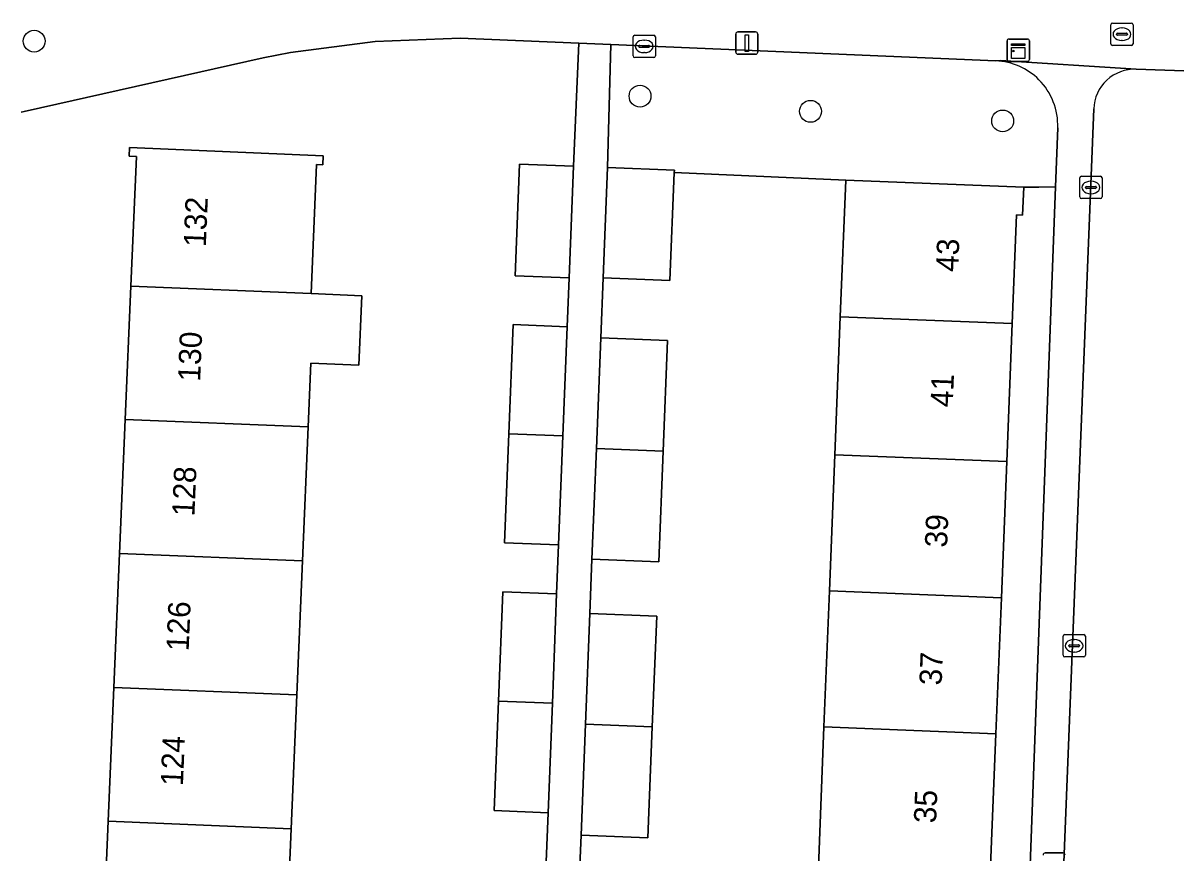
# Model space of a CAD drawing. Extents: x 161354 to 162026, y 386504 to 387460.
# Drawn here: x 161454.5 to 161506.1, y 387353.5 to 387390.7 of the extents above; entities that cross this region are included whole.
import ezdxf

# ---------------------------------------------------------------- set-up
doc = ezdxf.new("R2010")
doc.units = 0
for name, color, linetype in [('IMGEO_Boom', 7, 'Continuous'), ('IMGEO_Brandkraan', 7, 'Continuous'), ('IMGEO_Erf', 7, 'Continuous'), ('IMGEO_Groenvoorziening', 7, 'Continuous'), ('IMGEO_Kast', 7, 'Continuous'), ('IMGEO_Kolk', 7, 'Continuous'), ('IMGEO_Lichtmast', 7, 'Continuous'), ('IMGEO_Pand', 7, 'Continuous'), ('IMGEO_Pand_nummerreeks', 7, 'Continuous'), ('IMGEO_Rijbaan_lokaal_open', 7, 'Continuous'), ('IMGEO_Voetpad_open', 7, 'Continuous')]:
    doc.layers.add(name, color=color, linetype=linetype)

msp = doc.modelspace()

# ---------------------------------------------------------------- linework, layer by layer
at = {"layer": 'IMGEO_Boom'}
for centre in [(161454.969, 387389.906), (161482.122, 387387.443), (161489.765, 387386.761), (161498.375, 387386.331)]:
    msp.add_circle(centre, 0.489, dxfattribs=at)
at = {"layer": 'IMGEO_Brandkraan'}
for p, q in [((161503.221, 387389.789), (161503.221, 387390.641)), ((161503.296, 387390.715), (161504.148, 387390.715)), ((161503.709, 387390.495), (161503.734, 387390.495)), ((161504.222, 387390.641), (161504.222, 387389.789)), ((161503.48, 387390.209), (161503.48, 387390.221)), ((161503.918, 387390.172), (161503.52, 387390.172)), ((161503.523, 387390.258), (161503.921, 387390.258)), ((161503.964, 387390.221), (161503.964, 387390.209)), ((161504.148, 387389.715), (161503.296, 387389.715)), ((161503.732, 387389.935), (161503.707, 387389.935))]:
    msp.add_line(p, q, dxfattribs=at)
for points in [[(161503.221, 387389.789), (161503.221, 387390.641)], [(161503.296, 387390.715), (161504.148, 387390.715)], [(161504.222, 387390.641), (161504.222, 387389.789)], [(161504.148, 387389.715), (161503.296, 387389.715)]]:
    msp.add_lwpolyline(points, dxfattribs=at)
for centre, radius, start, end in [((161503.298, 387390.639), 0.0765, 91.552, 178.448), ((161503.298, 387390.639), 0.0765, 91.552, 178.448), ((161504.146, 387390.639), 0.0765, 1.552, 88.448), ((161504.146, 387390.639), 0.0765, 1.552, 88.448), ((161503.52, 387390.218), 0.0403, 85.8775, 175.7526), ((161503.517, 387390.208), 0.0366, 178.938, 274.7102), ((161503.921, 387390.215), 0.043, 264.8664, 352.4533), ((161503.925, 387390.22), 0.0386, 1.7309, 96.639), ((161503.298, 387389.791), 0.0765, 181.552, 268.448), ((161503.298, 387389.791), 0.0765, 181.552, 268.448), ((161504.146, 387389.791), 0.0765, 271.552, 358.448), ((161504.146, 387389.791), 0.0765, 271.552, 358.448)]:
    msp.add_arc(centre, radius, start, end, dxfattribs=at)
for centre, major_axis, ratio, start_param, end_param in [((161503.708, 387390.215), (-0.387, 0.002), 0.722429, 4.712389, 7.853982), ((161503.733, 387390.215), (-0.39, 0.002), 0.717154, 1.570796, 4.712389)]:
    msp.add_ellipse(centre, major_axis=major_axis, ratio=ratio, start_param=start_param, end_param=end_param, dxfattribs=at)
at = {"layer": 'IMGEO_Erf'}
for points in [[(161477.915, 387353.138), (161478.001, 387355.333), (161475.583, 387355.428), (161475.775, 387360.336), (161475.967, 387365.233), (161478.385, 387365.138), (161478.471, 387367.331), (161476.053, 387367.426), (161476.245, 387372.316), (161476.437, 387377.202), (161478.855, 387377.107), (161478.941, 387379.294), (161476.522, 387379.388), (161476.719, 387384.394), (161479.137, 387384.3), (161479.375, 387389.814), (161474.065, 387390.038), (161470.244, 387389.887), (161466.452, 387389.396), (161465.237, 387389.165), (161454.523, 387386.754), (161454.385, 387386.717)], [(161458.029, 387348.947), (161458.285, 387354.95), (161458.54, 387360.952), (161458.796, 387366.955), (161459.051, 387372.957), (161459.305, 387378.927), (161459.552, 387384.732), (161459.231, 387384.745), (161459.248, 387385.135), (161467.916, 387384.766), (161467.9, 387384.367), (161467.622, 387384.379), (161467.376, 387378.6), (161469.657, 387378.501), (161469.524, 387375.385), (161467.37, 387375.477), (161467.249, 387372.625), (161466.993, 387366.622), (161466.738, 387360.619), (161466.483, 387354.617), (161466.227, 387348.614)], [(161490.114, 387352.891), (161490.365, 387359.176), (161490.609, 387365.27), (161490.853, 387371.376), (161491.099, 387377.555), (161491.344, 387383.676), (161483.657, 387384.025), (161483.465, 387379.178), (161480.467, 387379.297), (161480.361, 387376.608), (161483.358, 387376.489), (161483.162, 387371.533), (161482.966, 387366.579), (161479.968, 387366.698), (161479.871, 387364.258), (161482.869, 387364.139), (161482.673, 387359.183), (161482.476, 387354.212), (161479.478, 387354.331), (161479.382, 387351.907)], [(161498.714, 387328.954), (161500, 387363.41), (161500.745, 387383.379), (161500, 387383.368), (161499.319, 387383.357), (161499.269, 387382.109), (161499.001, 387382.12), (161498.806, 387377.247), (161498.56, 387371.068), (161498.316, 387364.962), (161498.072, 387358.868), (161497.821, 387352.583)]]:
    msp.add_lwpolyline(points, dxfattribs=at)
at = {"layer": 'IMGEO_Groenvoorziening'}
msp.add_lwpolyline([(161498.068, 387389.025), (161480.807, 387389.753), (161480.663, 387384.24), (161483.661, 387384.122), (161483.657, 387384.025), (161491.344, 387383.676), (161499.319, 387383.357), (161500, 387383.368), (161500.745, 387383.379), (161500.844, 387386.024)], dxfattribs=at)
for centre, radius, start, end in [((161497.945, 387386.118), 2.909, 45.0688, 87.5853), ((161497.921, 387386.121), 2.925, 358.1019, 44.6915)]:
    msp.add_arc(centre, radius, start, end, dxfattribs=at)
at = {"layer": 'IMGEO_Kast'}
for p, q in [((161498.648, 387389.999), (161499.489, 387389.999)), ((161499.489, 387389.999), (161498.648, 387389.999)), ((161498.573, 387389.074), (161498.573, 387389.915)), ((161498.573, 387389.915), (161498.573, 387389.074)), ((161499.573, 387389.924), (161499.573, 387389.083)), ((161499.573, 387389.083), (161499.573, 387389.924)), ((161499.498, 387388.999), (161498.657, 387388.999)), ((161498.657, 387388.999), (161499.498, 387388.999))]:
    msp.add_line(p, q, dxfattribs=at)
for points in [[(161498.768, 387389.789), (161499.368, 387389.789), (161499.368, 387389.704), (161498.768, 387389.704), (161498.768, 387389.789)], [(161498.768, 387389.614), (161499.368, 387389.614), (161499.368, 387389.125), (161498.768, 387389.125), (161498.768, 387389.614)]]:
    msp.add_lwpolyline(points, dxfattribs=at)
msp.add_circle((161498.852, 387389.463), 0.0377, dxfattribs=at)
for centre, start, end in [((161498.651, 387389.921), 92.4484, 184.2845), ((161498.651, 387389.921), 92.4484, 184.2845), ((161499.495, 387389.921), 2.4484, 94.2845), ((161499.495, 387389.921), 2.4484, 94.2845), ((161498.651, 387389.077), 182.4484, 274.2845), ((161498.651, 387389.077), 182.4484, 274.2845), ((161499.495, 387389.077), 272.4484, 4.2845), ((161499.495, 387389.077), 272.4484, 4.2845)]:
    msp.add_arc(centre, 0.0779, start, end, dxfattribs=at)
at = {"layer": 'IMGEO_Kolk'}
for p, q in [((161481.808, 387389.245), (161481.808, 387390.097)), ((161481.883, 387390.171), (161482.735, 387390.171)), ((161482.809, 387390.097), (161482.809, 387389.245)), ((161482.067, 387389.665), (161482.067, 387389.677)), ((161482.505, 387389.628), (161482.107, 387389.628)), ((161482.11, 387389.714), (161482.508, 387389.714)), ((161482.296, 387389.951), (161482.321, 387389.951)), ((161482.551, 387389.677), (161482.551, 387389.665)), ((161482.735, 387389.171), (161481.883, 387389.171)), ((161482.319, 387389.391), (161482.294, 387389.391)), ((161501.83, 387382.925), (161501.83, 387383.777)), ((161501.905, 387383.851), (161502.757, 387383.851)), ((161502.831, 387383.777), (161502.831, 387382.925)), ((161502.089, 387383.345), (161502.089, 387383.357)), ((161502.527, 387383.308), (161502.129, 387383.308)), ((161502.132, 387383.394), (161502.53, 387383.394)), ((161502.318, 387383.631), (161502.343, 387383.631)), ((161502.573, 387383.357), (161502.573, 387383.345)), ((161502.757, 387382.851), (161501.905, 387382.851)), ((161502.341, 387383.071), (161502.316, 387383.071)), ((161501.079, 387362.388), (161501.079, 387363.24)), ((161501.154, 387363.314), (161502.006, 387363.314)), ((161502.08, 387363.24), (161502.08, 387362.388)), ((161501.338, 387362.808), (161501.338, 387362.82)), ((161501.776, 387362.771), (161501.378, 387362.771)), ((161501.381, 387362.857), (161501.779, 387362.857)), ((161501.567, 387363.094), (161501.592, 387363.094)), ((161501.822, 387362.82), (161501.822, 387362.808)), ((161502.006, 387362.314), (161501.154, 387362.314)), ((161501.59, 387362.534), (161501.565, 387362.534))]:
    msp.add_line(p, q, dxfattribs=at)
for points in [[(161481.808, 387389.245), (161481.808, 387390.097)], [(161481.883, 387390.171), (161482.735, 387390.171)], [(161482.809, 387390.097), (161482.809, 387389.245)], [(161482.735, 387389.171), (161481.883, 387389.171)], [(161501.83, 387382.925), (161501.83, 387383.777)], [(161501.905, 387383.851), (161502.757, 387383.851)], [(161502.831, 387383.777), (161502.831, 387382.925)], [(161502.757, 387382.851), (161501.905, 387382.851)], [(161501.079, 387362.388), (161501.079, 387363.24)], [(161501.154, 387363.314), (161502.006, 387363.314)], [(161502.08, 387363.24), (161502.08, 387362.388)], [(161502.006, 387362.314), (161501.154, 387362.314)]]:
    msp.add_lwpolyline(points, dxfattribs=at)
for centre, radius, start, end in [((161481.885, 387390.095), 0.0765, 91.552, 178.448), ((161481.885, 387390.095), 0.0765, 91.552, 178.448), ((161482.733, 387390.095), 0.0765, 1.552, 88.448), ((161482.733, 387390.095), 0.0765, 1.552, 88.448), ((161482.107, 387389.674), 0.0403, 85.8775, 175.7526), ((161482.104, 387389.664), 0.0366, 178.938, 274.7102), ((161482.508, 387389.671), 0.043, 264.8664, 352.4533), ((161482.512, 387389.676), 0.0386, 1.7309, 96.639), ((161481.885, 387389.247), 0.0765, 181.552, 268.448), ((161481.885, 387389.247), 0.0765, 181.552, 268.448), ((161482.733, 387389.247), 0.0765, 271.552, 358.448), ((161482.733, 387389.247), 0.0765, 271.552, 358.448), ((161501.907, 387383.775), 0.0765, 91.552, 178.448), ((161501.907, 387383.775), 0.0765, 91.552, 178.448), ((161502.755, 387383.775), 0.0765, 1.552, 88.448), ((161502.755, 387383.775), 0.0765, 1.552, 88.448), ((161502.129, 387383.354), 0.0403, 85.8775, 175.7526), ((161502.126, 387383.344), 0.0366, 178.938, 274.7102), ((161502.53, 387383.351), 0.043, 264.8664, 352.4533), ((161502.534, 387383.356), 0.0386, 1.7309, 96.639), ((161501.907, 387382.927), 0.0765, 181.552, 268.448), ((161501.907, 387382.927), 0.0765, 181.552, 268.448), ((161502.755, 387382.927), 0.0765, 271.552, 358.448), ((161502.755, 387382.927), 0.0765, 271.552, 358.448), ((161501.156, 387363.238), 0.0765, 91.552, 178.448), ((161501.156, 387363.238), 0.0765, 91.552, 178.448), ((161502.004, 387363.238), 0.0765, 1.552, 88.448), ((161502.004, 387363.238), 0.0765, 1.552, 88.448), ((161501.378, 387362.817), 0.0403, 85.8775, 175.7526), ((161501.375, 387362.807), 0.0366, 178.938, 274.7102), ((161501.779, 387362.814), 0.043, 264.8664, 352.4533), ((161501.783, 387362.819), 0.0386, 1.7309, 96.639), ((161501.156, 387362.39), 0.0765, 181.552, 268.448), ((161501.156, 387362.39), 0.0765, 181.552, 268.448), ((161502.004, 387362.39), 0.0765, 271.552, 358.448), ((161502.004, 387362.39), 0.0765, 271.552, 358.448)]:
    msp.add_arc(centre, radius, start, end, dxfattribs=at)
for centre, major_axis, ratio, start_param, end_param in [((161482.295, 387389.671), (-0.387, 0.002), 0.722429, 4.712389, 7.853982), ((161482.32, 387389.671), (-0.39, 0.002), 0.717154, 1.570796, 4.712389), ((161502.317, 387383.351), (-0.387, 0.002), 0.722429, 4.712389, 7.853982), ((161502.342, 387383.351), (-0.39, 0.002), 0.717154, 1.570796, 4.712389), ((161501.566, 387362.814), (-0.387, 0.002), 0.722429, 4.712389, 7.853982), ((161501.591, 387362.814), (-0.39, 0.002), 0.717154, 1.570796, 4.712389)]:
    msp.add_ellipse(centre, major_axis=major_axis, ratio=ratio, start_param=start_param, end_param=end_param, dxfattribs=at)
at = {"layer": 'IMGEO_Lichtmast'}
for p, q in [((161486.411, 387389.417), (161486.411, 387390.217)), ((161486.411, 387390.217), (161486.411, 387389.417)), ((161486.511, 387390.317), (161487.301, 387390.317)), ((161487.301, 387390.317), (161486.511, 387390.317)), ((161487.401, 387390.217), (161487.401, 387389.417)), ((161487.401, 387389.417), (161487.401, 387390.217)), ((161487.301, 387389.317), (161486.511, 387389.317)), ((161486.511, 387389.317), (161487.301, 387389.317)), ((161500.284, 387353.533), (161501.074, 387353.533)), ((161501.074, 387353.533), (161500.284, 387353.533))]:
    msp.add_line(p, q, dxfattribs=at)
msp.add_lwpolyline([(161486.831, 387390.192), (161486.981, 387390.192), (161486.981, 387389.442), (161486.831, 387389.442), (161486.831, 387390.192)], dxfattribs=at)
for centre, start, end in [((161486.511, 387390.217), 90, 180), ((161486.511, 387390.217), 90, 180), ((161487.301, 387390.217), 0, 90), ((161487.301, 387390.217), 360, 90), ((161486.511, 387389.417), 180, 270), ((161486.511, 387389.417), 180, 270), ((161487.301, 387389.417), 270, 0), ((161487.301, 387389.417), 270, 0), ((161500.284, 387353.433), 90, 180), ((161500.284, 387353.433), 90, 180), ((161501.074, 387353.433), 0, 90), ((161501.074, 387353.433), 360, 90)]:
    msp.add_arc(centre, 0.1, start, end, dxfattribs=at)
at = {"layer": 'IMGEO_Pand'}
for points in [[(161467.376, 387378.6), (161467.622, 387384.379), (161467.9, 387384.367), (161467.916, 387384.766), (161459.248, 387385.135), (161459.231, 387384.745), (161459.552, 387384.732), (161459.305, 387378.927)], [(161479.137, 387384.3), (161476.719, 387384.394), (161476.522, 387379.388), (161478.941, 387379.294)], [(161483.657, 387384.025), (161483.661, 387384.122), (161480.663, 387384.24), (161480.467, 387379.297), (161483.465, 387379.178)], [(161491.344, 387383.676), (161491.099, 387377.555), (161498.806, 387377.247), (161499.001, 387382.12), (161499.269, 387382.109), (161499.319, 387383.357)], [(161467.249, 387372.625), (161467.37, 387375.477), (161469.524, 387375.385), (161469.657, 387378.501), (161467.376, 387378.6), (161459.305, 387378.927), (161459.051, 387372.957)], [(161478.855, 387377.107), (161476.437, 387377.202), (161476.245, 387372.316), (161478.663, 387372.221)], [(161491.099, 387377.555), (161490.853, 387371.376), (161498.56, 387371.068), (161498.806, 387377.247)], [(161480.361, 387376.608), (161480.164, 387371.652), (161483.162, 387371.533), (161483.358, 387376.489)], [(161459.051, 387372.957), (161458.796, 387366.955), (161466.993, 387366.622), (161467.249, 387372.625)], [(161478.663, 387372.221), (161476.245, 387372.316), (161476.053, 387367.426), (161478.471, 387367.331)], [(161483.162, 387371.533), (161480.164, 387371.652), (161479.968, 387366.698), (161482.966, 387366.579)], [(161490.853, 387371.376), (161490.609, 387365.27), (161498.316, 387364.962), (161498.56, 387371.068)], [(161466.738, 387360.619), (161466.993, 387366.622), (161458.796, 387366.955), (161458.54, 387360.952)], [(161478.385, 387365.138), (161475.967, 387365.233), (161475.775, 387360.336), (161478.193, 387360.241)], [(161498.072, 387358.868), (161498.316, 387364.962), (161490.609, 387365.27), (161490.365, 387359.176)], [(161479.871, 387364.258), (161479.675, 387359.302), (161482.673, 387359.183), (161482.869, 387364.139)], [(161458.54, 387360.952), (161458.285, 387354.95), (161466.483, 387354.617), (161466.738, 387360.619)], [(161478.193, 387360.241), (161475.775, 387360.336), (161475.583, 387355.428), (161478.001, 387355.333)], [(161482.673, 387359.183), (161479.675, 387359.302), (161479.478, 387354.331), (161482.476, 387354.212)], [(161490.365, 387359.176), (161490.114, 387352.891), (161497.821, 387352.583), (161498.072, 387358.868)], [(161458.285, 387354.95), (161458.029, 387348.947), (161466.227, 387348.614), (161466.483, 387354.617)]]:
    msp.add_lwpolyline(points, close=True, dxfattribs=at)
at = {"layer": 'IMGEO_Rijbaan_lokaal_open'}
for points in [[(161517.618, 387388.189), (161504.363, 387388.647)], [(161502.454, 387386.874), (161500.117, 387327.957), (161499.877, 387322.239), (161499.07, 387300.302)]]:
    msp.add_lwpolyline(points, dxfattribs=at)
msp.add_arc((161504.294, 387386.807), 1.842, 87.862, 177.9073, dxfattribs=at)
at = {"layer": 'IMGEO_Voetpad_open'}
for points in [[(161454.385, 387386.717), (161454.523, 387386.754), (161465.237, 387389.165), (161466.452, 387389.396), (161470.244, 387389.887), (161474.065, 387390.038), (161479.375, 387389.814), (161480.807, 387389.753), (161498.068, 387389.025), (161498.271, 387389.032), (161504.363, 387388.647), (161517.618, 387388.189)], [(161479.382, 387351.907), (161479.478, 387354.331), (161479.675, 387359.302), (161479.871, 387364.258), (161479.968, 387366.698), (161480.164, 387371.652), (161480.361, 387376.608), (161480.467, 387379.297), (161480.663, 387384.24), (161480.807, 387389.753), (161479.375, 387389.814), (161479.137, 387384.3), (161478.941, 387379.294), (161478.855, 387377.107), (161478.663, 387372.221), (161478.471, 387367.331), (161478.385, 387365.138), (161478.193, 387360.241), (161478.001, 387355.333), (161477.915, 387353.138)], [(161504.363, 387388.647), (161498.271, 387389.032), (161498.068, 387389.025)], [(161500.844, 387386.024), (161500.745, 387383.379), (161500, 387363.41), (161498.714, 387328.954), (161498.68, 387328.024), (161500.117, 387327.957), (161502.454, 387386.874)]]:
    msp.add_lwpolyline(points, dxfattribs=at)
for centre, radius, start, end in [((161497.945, 387386.118), 2.909, 45.0688, 87.5853), ((161504.294, 387386.807), 1.842, 87.862, 177.9073), ((161497.921, 387386.121), 2.925, 358.1019, 44.6915)]:
    msp.add_arc(centre, radius, start, end, dxfattribs=at)

# ---------------------------------------------------------------- texts
at = {"layer": 'IMGEO_Pand_nummerreeks'}
for s, rotation, p in [('132', 87.5637, (161462.661, 387380.674)), ('43', 87.713, (161496.377, 387379.555)), ('130', 87.5637, (161462.406, 387374.641)), ('41', 87.713, (161496.135, 387373.492)), ('128', 87.5637, (161462.149, 387368.602)), ('39', 87.713, (161495.884, 387367.203)), ('126', 87.5637, (161461.891, 387362.559)), ('37', 87.713, (161495.637, 387361.027)), ('124', 87.5637, (161461.634, 387356.52)), ('35', 87.713, (161495.39, 387354.851))]:
    msp.add_text(s, height=1, rotation=rotation, dxfattribs=at).set_placement(p)

doc.saveas('drawing.dxf')
